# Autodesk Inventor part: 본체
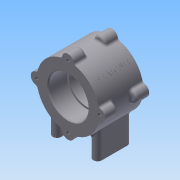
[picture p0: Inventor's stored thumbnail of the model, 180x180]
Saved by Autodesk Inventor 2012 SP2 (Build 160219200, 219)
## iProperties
Created: 2015-03
Part Number: 본체
Material: 알루미늄-6061
Document SubType Name: Modeling
Designer: Administrator
Density: 2.71 g/cm^3
Mass: 450.782 g
Surface Area: 332.69 cm^2
Volume: 166.34 cm^3
Author: Administrator
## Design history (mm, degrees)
sketch "스케치2"
  geometry: L1 (-26, 0)-(26, 0); L2 (-26, 0)-(-26, 37); L3 (-26, 37)-(26, 37); L4 (26, 37)-(26, 0); 2 further points
  constraints: 8 end point, 3 perpendicular, 2 coincident, 1 horizontal, 1 midpoint
  dimensions: "d1" = 52 distance of L1.start L1.end; "d2" = 74 diameter of L3 L1
revolve "회전1" sketch "스케치2" stored, may be unused: angle "d3" = 90 deg
sketch "스케치8"
  geometry: L1 (37, -26)-(-37, -26) reference; L2 (-37, -26)-(-37, 26) reference; L3 (-37, 26)-(37, 26) reference; L4 (37, 26)-(37, -26) reference; L5 (0, 26)-(0, -26); L6 (-29, 15)-(-29, -15); L7 (-29, -15)-(-19, -15); L8 (-19, -15)-(-19, 15); L9 (-19, 15)-(-29, 15); L10 (19, 15)-(19, -15); L11 (19, -15)-(29, -15); L12 (29, -15)-(29, 15); L13 (29, 15)-(19, 15); L14 (-37, 0)-(37, 0); A1 r 5 centre (-24, 15) between (-19, 15) and (-29, 15); A2 r 5 centre (24, 15) between (29, 15) and (19, 15); A3 r 5 centre (24, -15) between (19, -15) and (29, -15); A4 r 5 centre (-24, -15) between (-29, -15) and (-19, -15); 1 further point
  constraints: 20 end point, 8 midpoint, 8 point on circle, 4 centre point, 4 horizontal, 2 vertical, 1 parallel, 1 perpendicular, 3 other
  dimensions: "d42" = 38 distance between parallel lines of L8 L10; "d43" = 10 distance between parallel lines of L8 L6; "d44" = 10 distance between parallel lines of L12 L10; "d45" = 30 distance of A4.centre A1.centre; "d46" = 30 distance between parallel lines of L13 L11
extrude "돌출2" join sketch "스케치8" distance "d47" = 56; taper "d48" = 0 deg
sketch "스케치4"
  geometry: L1 (-26, -37)-(-26, 37) reference; L2 (-26, 37)-(26, 37) reference; L3 (26, 37)-(26, -37) reference; L4 (26, -37)-(-26, -37) reference; L5 (-25.085, 37)-(26, 37); L6 (-26, 37)-(-26, 44); L7 (-26, 44)-(-14, 44); L8 (-11, 41)-(-11, 37); L9 (26, 37)-(26, 44); L10 (26, 44)-(14, 44); L11 (11, 41)-(11, 37); A1 r 3 centre (-14, 41) between (-11, 41) and (-14, 44); A2 r 3 centre (14, 41) between (14, 44) and (11, 41); 3 further points
  constraints: 14 end point, 7 point on line, 6 perpendicular, 4 point on circle, 4 tangent, 2 centre point, 1 equal radius, 1 horizontal alignment, 1 parallel
  dimensions: "d10" = 14 diameter of L7 L2; "d11" = 15 distance between parallel lines of L6 L8; "d12" = 15 distance between parallel lines of L9 L11; "d13" = 3 radius of A1
revolve "회전2" sketch "스케치4" stored, may be unused: angle "d14" = 90 deg
sketch "스케치5"
  geometry: L1 (-11, 41)-(-11, 37) reference; L2 (-11, 37)-(11, 37) reference; L3 (11, 37)-(11, 41) reference; L4 (14, 44)-(26, 44) reference; L5 (26, 44)-(26, -44) reference; L6 (26, -44)-(14, -44) reference; L7 (11, -41)-(11, -37) reference; L8 (11, -37)-(-11, -37) reference; L9 (-11, -37)-(-11, -41) reference; L10 (-14, -44)-(-26, -44) reference; L11 (-26, -44)-(-26, 44) reference; L12 (-26, 44)-(-14, 44) reference; L13 (-26, 0)-(26, 0); L14 (-25, 23.5)-(-4.3, 23.5); L15 (-4, 23.2)-(-4, 21); L16 (-4, 21)-(4, 21); L17 (4, 21)-(4, 23.2); L18 (4.3, 23.5)-(25, 23.5); L19 (-25, 23.5)-(-26, 24.5); L20 (25, 23.5)-(26, 24.5); L21 (-26, 24.5)-(-26, 0); L22 (26, 0)-(26, 24.5); A1 r 3 centre (-14, 41) between (-11, 41) and (-14, 44) reference; A2 r 3 centre (14, 41) between (14, 44) and (11, 41) reference; A3 r 3 centre (14, -41) between (11, -41) and (14, -44) reference; A4 r 3 centre (-14, -41) between (-14, -44) and (-11, -41) reference; A5 r 0.3 centre (-4.3, 23.2) between (-4, 23.2) and (-4.3, 23.5); A6 r 0.3 centre (4.3, 23.2) between (4.3, 23.5) and (4, 23.2); 5 further points
  constraints: 20 end point, 10 point on line, 4 parallel, 4 point on circle, 4 tangent, 2 centre point, 2 midpoint, 2 perpendicular, 1 collinear, 1 equal radius, 1 horizontal alignment
  dimensions: "d18" = 22 distance between parallel lines of L11 L15; "d19" = 22 distance between parallel lines of L5 L17; "d20" = 47 diameter of L14 L13; "d21" = 42 diameter of L16 L13; "d22" = 0.3 radius of A5; "d23" = 1 distance of L14.start point (-26, 23.5); "d24" = 45 deg angle of L14 L19; "d25" = 1 distance of L18.end point (26, 23.5); "d26" = 45 deg angle of L18 L20
revolve "회전3" sketch "스케치5" stored, may be unused: angle "d27" = 90 deg
sketch "스케치6"
  geometry: A1 r 7 centre (0, -74) between (-6.969, -73.338) and (6.969, -73.338) reference; A2 r 7 centre (37, -37) between (36.338, -43.969) and (36.338, -30.031) reference; A3 r 7 centre (0, 0) between (6.969, -0.662) and (-6.969, -0.662) reference; A4 r 7 centre (-37, -37) between (-36.338, -30.031) and (-36.338, -43.969) reference; 4 further points
  constraints: 4 coincident
hole "구멍1" sketch "스케치6" at (0, 0), (37, -37), (0, -74), (-37, -37) diameter "d28" = 3.242; stored, may be unused: countersink angle "d32" = 90 deg, drill point angle "d34" = 118 deg; dims "d29" = 8, "d30" = 4, "d31" = 2, "d33" = 11
sketch "스케치7"
  geometry: A1 r 7 centre (0, 0) between (-6.969, 0.662) and (6.969, 0.662) reference; A2 r 7 centre (37, 37) between (36.338, 30.031) and (36.338, 43.969) reference; A3 r 7 centre (0, 74) between (6.969, 73.338) and (-6.969, 73.338) reference; A4 r 7 centre (-37, 37) between (-36.338, 43.969) and (-36.338, 30.031) reference; 4 further points
  constraints: 4 coincident
hole "구멍2" sketch "스케치7" at (0, 74), (37, 37), (0, 0), (-37, 37) diameter "d35" = 3.242; stored, may be unused: countersink angle "d39" = 90 deg, drill point angle "d41" = 118 deg; dims "d36" = 8, "d37" = 4, "d38" = 2, "d40" = 11
sketch "스케치9"
  geometry: L1 (-29, -15)-(-29, 15) reference; L2 (-19, 15)-(-19, -15) reference; L3 (19, -15)-(19, 15) reference; L4 (29, 15)-(29, -15) reference; A1 r 5 centre (-24, 15) between (-19, 15) and (-29, 15) reference; A2 r 5 centre (-24, -15) between (-29, -15) and (-19, -15) reference; A3 r 5 centre (24, 15) between (29, 15) and (19, 15) reference; A4 r 5 centre (24, -15) between (19, -15) and (29, -15) reference; 5 further points
  constraints: 4 coincident
hole "구멍3" sketch "스케치9" at (-24, 15), (24, 15), (24, -15), (-24, -15) diameter "d49" = 4.134; stored, may be unused: countersink angle "d53" = 90 deg, drill point angle "d55" = 118 deg; dims "d50" = 6, "d51" = 4, "d52" = 2, "d54" = 8
fillet "모깎기1" dims "d56" = 3
node "작업 평면2"
sketch "스케치11"
  geometry: L1 (0, -18.921)-(0, 18.921) reference; 2 further points
  constraints: 1 coincident, 1 other
  dimensions: "d59" = 26 distance from line of L1 point (26, 0)
feature "엠보싱1" sketch "스케치11" dims "d1" = 52, "d2" = 74, "d60" = 0.5, "d61" = 0
node "솔리드1"
pattern_circular "원형 패턴1" dims angle "d16" = 360 deg
node "절단 모서리 투영2"
node "절단 모서리 투영3"
node "절단 모서리 투영4"
node "절단 모서리 투영5"
